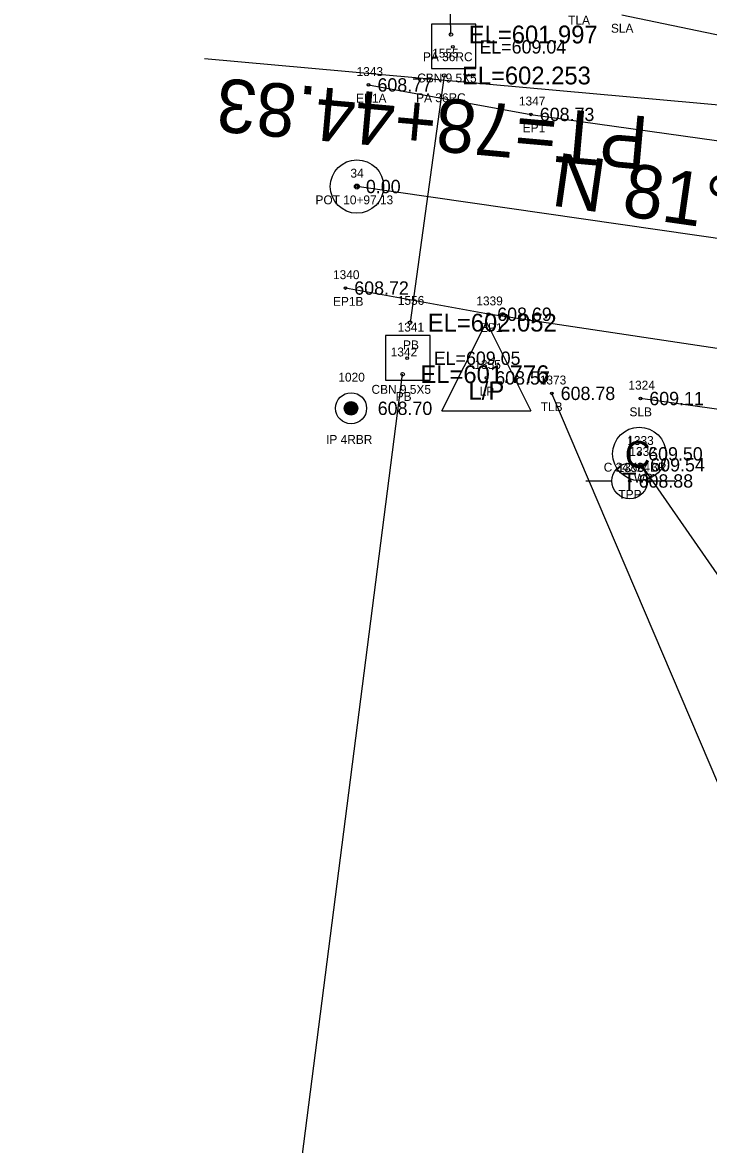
# Model space of a CAD drawing. Extents: x 1694813 to 1696862, y 1086485 to 1091027.
# Drawn here: x 1695695 to 1695772.2, y 1089855.4 to 1089981.5 of the extents above; entities that cross this region are included whole.
import ezdxf

# ---------------------------------------------------------------- set-up
doc = ezdxf.new("R2010")
doc.units = 0
for name, color, linetype in [('RD_EX_BldgApp', 7, 'Continuous'), ('RD_EX_BldgApp_txCode', 7, 'Continuous'), ('RD_EX_DR_Inlet', 7, 'Continuous'), ('RD_EX_DR_Inlet_txCode', 7, 'Continuous'), ('RD_EX_DR_Pipe', 7, 'Continuous'), ('RD_EX_DR_Pipe_txCode', 7, 'Continuous'), ('RD_EX_DV_Prop_txCode', 7, 'Continuous'), ('RD_EX_DV_PropPin', 7, 'Continuous'), ('RD_EX_Misc_txCode', 7, 'Continuous'), ('RD_EX_Road', 7, 'Continuous'), ('RD_EX_Road_txCode', 7, 'Continuous'), ('RD_EX_TX_BldgApp_ELEV', 7, 'Continuous'), ('RD_EX_TX_DR_Inlet_ELEV', 7, 'Continuous'), ('RD_EX_TX_DV_Prop_ELEV', 7, 'Continuous'), ('RD_EX_TX_Misc_ELEV', 7, 'Continuous'), ('RD_EX_TX_Road_ELEV', 7, 'Continuous'), ('RD_EX_TX_UT_ELEV', 7, 'Continuous'), ('RD_EX_TX_VEG_ELEV', 7, 'Continuous'), ('RD_EX_UT', 7, 'Continuous'), ('RD_EX_UT_txCode', 7, 'Continuous'), ('RD_EX_VEG', 7, 'Continuous'), ('RD_EX_VEG_txCode', 7, 'Continuous'), ('RD_HC_Cl', 7, 'Continuous'), ('RD_HC_Data', 7, 'Continuous'), ('RD_HC_Survey_ELEV', 7, 'Continuous'), ('RD_HC_txCode', 7, 'Continuous'), ('RD_SMD_Locator', 7, 'Continuous'), ('RD_TX_Pipe_ElevEX', 7, 'Continuous')]:
    doc.layers.add(name, color=color, linetype=linetype)

msp = doc.modelspace()

# ---------------------------------------------------------------- linework, layer by layer
at = {"layer": 'RD_EX_BldgApp'}
msp.add_line((1695785.88, 1089901.2), (1695764.63, 1089931.79), dxfattribs=at)
msp.add_circle((1695764.39, 1089933.02), 3, dxfattribs=at)
at = {"layer": 'RD_EX_DR_Inlet'}
for p, q in [((1695746, 1089976.32), (1695746, 1089981.32)), ((1695740.86, 1089941.32), (1695740.86, 1089946.32))]:
    msp.add_line(p, q, dxfattribs=at)
for points in [[(1695746, 1089976.32), (1695746, 1089981.32), (1695741, 1089981.32), (1695741, 1089976.32)], [(1695740.86, 1089941.32), (1695740.86, 1089946.32), (1695735.86, 1089946.32), (1695735.86, 1089941.32)]]:
    msp.add_lwpolyline(points, close=True, dxfattribs=at)
at = {"layer": 'RD_EX_DR_Pipe'}
for p, q in [((1695743.21, 1089980.16), (1695742.39, 1090020.71)), ((1695742.44, 1089975.55), (1695738.6, 1089947.77)), ((1695713.87, 1089755.91), (1695737.77, 1089941.97))]:
    msp.add_line(p, q, dxfattribs=at)
at = {"layer": 'RD_EX_DV_PropPin'}
for p, q in [((1695731.27, 1089937.84), (1695731.27, 1089938.44)), ((1695731.3, 1089937.77), (1695731.3, 1089938.51)), ((1695731.34, 1089937.71), (1695731.34, 1089938.57)), ((1695731.37, 1089937.66), (1695731.37, 1089938.61)), ((1695731.41, 1089937.62), (1695731.41, 1089938.65)), ((1695731.44, 1089937.59), (1695731.44, 1089938.69)), ((1695731.48, 1089937.56), (1695731.48, 1089938.72)), ((1695731.51, 1089937.53), (1695731.51, 1089938.75)), ((1695731.55, 1089937.5), (1695731.55, 1089938.77)), ((1695731.58, 1089937.48), (1695731.58, 1089938.79)), ((1695731.62, 1089937.46), (1695731.62, 1089938.81)), ((1695731.65, 1089937.45), (1695731.65, 1089938.83)), ((1695731.69, 1089937.43), (1695731.69, 1089938.85)), ((1695731.72, 1089937.42), (1695731.72, 1089938.86)), ((1695731.76, 1089937.41), (1695731.76, 1089938.87)), ((1695731.79, 1089937.4), (1695731.79, 1089938.88)), ((1695731.83, 1089937.39), (1695731.83, 1089938.89)), ((1695731.86, 1089937.38), (1695731.86, 1089938.89)), ((1695731.9, 1089937.38), (1695731.9, 1089938.9)), ((1695731.93, 1089937.38), (1695731.93, 1089938.9)), ((1695731.97, 1089937.38), (1695731.97, 1089938.9)), ((1695732, 1089937.38), (1695732, 1089938.9)), ((1695732.04, 1089937.38), (1695732.04, 1089938.9)), ((1695732.07, 1089937.38), (1695732.07, 1089938.89)), ((1695732.11, 1089937.39), (1695732.11, 1089938.89)), ((1695732.14, 1089937.4), (1695732.14, 1089938.88)), ((1695732.18, 1089937.41), (1695732.18, 1089938.87)), ((1695732.21, 1089937.42), (1695732.21, 1089938.86)), ((1695732.25, 1089937.43), (1695732.25, 1089938.85)), ((1695732.28, 1089937.45), (1695732.28, 1089938.83)), ((1695732.32, 1089937.46), (1695732.32, 1089938.81)), ((1695732.35, 1089937.48), (1695732.35, 1089938.79)), ((1695732.39, 1089937.5), (1695732.39, 1089938.77)), ((1695732.42, 1089937.53), (1695732.42, 1089938.75)), ((1695732.46, 1089937.56), (1695732.46, 1089938.72)), ((1695732.49, 1089937.59), (1695732.49, 1089938.69)), ((1695732.53, 1089937.62), (1695732.53, 1089938.65)), ((1695732.56, 1089937.66), (1695732.56, 1089938.61)), ((1695732.6, 1089937.71), (1695732.6, 1089938.57)), ((1695732.63, 1089937.77), (1695732.63, 1089938.51)), ((1695732.67, 1089937.84), (1695732.67, 1089938.44)), ((1695731.23, 1089937.94), (1695731.23, 1089938.33)), ((1695732.7, 1089937.94), (1695732.7, 1089938.33))]:
    msp.add_line(p, q, dxfattribs=at)
for radius in [1.75, 0.761]:
    msp.add_circle((1695731.97, 1089938.14), radius, dxfattribs=at)
at = {"layer": 'RD_EX_Road'}
for points in [[(1695733.94, 1089974.49), (1695752.2, 1089971.18), (1695799.58, 1089964.52), (1695808.15, 1089966.05), (1695812.58, 1089968.74), (1695812.72, 1089971.11), (1695815.83, 1089973.5), (1695820.51, 1089978.16)], [(1695814.71, 1089923.3), (1695809.51, 1089930.83), (1695802.46, 1089937.48), (1695803.12, 1089939.11), (1695792.87, 1089941.91), (1695747.41, 1089948.71), (1695731.33, 1089951.66)]]:
    msp.add_lwpolyline(points, dxfattribs=at)
at = {"layer": 'RD_EX_UT'}
for p, q in [((1695742.19, 1089937.84), (1695747.19, 1089947.84)), ((1695747.19, 1089947.84), (1695752.19, 1089937.84)), ((1695742.19, 1089937.84), (1695752.19, 1089937.84)), ((1695763.31, 1089935.04), (1695763.31, 1089931.97)), ((1695758.38, 1089929.98), (1695761.31, 1089929.98)), ((1695765.31, 1089929.98), (1695768.38, 1089929.98))]:
    msp.add_line(p, q, dxfattribs=at)
msp.add_circle((1695763.31, 1089929.97), 2, dxfattribs=at)
at = {"layer": 'RD_EX_VEG'}
for points in [[(1695762.44, 1089982.36), (1695791.84, 1089976.26), (1695804.67, 1089985.58), (1695805.61, 1090018.45), (1695818.68, 1090120.45), (1695830.78, 1090219.77), (1695838.1, 1090274.39)], [(1695703.52, 1089329.03), (1695695, 1089381.13), (1695696.39, 1089435.79), (1695702.88, 1089488.39), (1695714.38, 1089541.02), (1695736.44, 1089639.8), (1695727.2, 1089683.67), (1695743.97, 1089747.86), (1695756.74, 1089783.05), (1695766.78, 1089823.73), (1695779.53, 1089881.29), (1695754.55, 1089939.82)], [(1695775.83, 1089809.76), (1695787.59, 1089876.92), (1695797.35, 1089923.06), (1695786.71, 1089936.12), (1695764.52, 1089939.24)]]:
    msp.add_lwpolyline(points, dxfattribs=at)
at = {"layer": 'RD_HC_Cl'}
msp.add_line((1695828.78, 1089949.26), (1695732.63, 1089963.07), dxfattribs=at)
at = {"layer": 'RD_HC_Data'}
msp.add_line((1695830.5, 1089967.08), (1695715.49, 1089977.42), dxfattribs=at)
for radius in [3, 0.282]:
    msp.add_circle((1695732.63, 1089963.07), radius, dxfattribs=at)
at = {"layer": 'RD_SMD_Locator'}
for centre, radius in [((1695743.21, 1089980.16), 0.2), ((1695743.41, 1089978.77), 0.15), ((1695742.44, 1089975.55), 0.2), ((1695733.94, 1089974.49), 0.15), ((1695752.2, 1089971.18), 0.15), ((1695732.63, 1089963.07), 0.15), ((1695731.33, 1089951.66), 0.15), ((1695747.41, 1089948.71), 0.15), ((1695738.6, 1089947.77), 0.2), ((1695738.27, 1089943.77), 0.15), ((1695737.77, 1089941.97), 0.2), ((1695747.19, 1089941.56), 0.15), ((1695754.55, 1089939.82), 0.15), ((1695764.52, 1089939.24), 0.15), ((1695731.97, 1089938.14), 0.15), ((1695764.39, 1089933.02), 0.15), ((1695764.63, 1089931.79), 0.15), ((1695763.31, 1089929.97), 0.15)]:
    msp.add_circle(centre, radius, dxfattribs=at)

# ---------------------------------------------------------------- texts
at = {"layer": 'RD_EX_BldgApp'}
msp.add_text('C', height=3, dxfattribs=at).set_placement((1695762.76, 1089931.46))
at = {"layer": 'RD_EX_BldgApp_txCode'}
for s, p in [('1333', (1695763.04, 1089934.02)), ('C 24X24BR', (1695760.39, 1089931.02))]:
    msp.add_text(s, height=1, dxfattribs=at).set_placement(p)
at = {"layer": 'RD_EX_DR_Inlet_txCode'}
for s, p in [('CBN 9 5X5', (1695739.41, 1089974.77)), ('1341', (1695737.21, 1089946.77)), ('CBN 9 5X5', (1695734.27, 1089939.77))]:
    msp.add_text(s, height=1, dxfattribs=at).set_placement(p)
at = {"layer": 'RD_EX_DR_Pipe_txCode'}
for s, p in [('PA 36RC', (1695740.06, 1089977.16)), ('1555', (1695741.09, 1089977.55)), ('PA 36RC', (1695739.29, 1089972.55)), ('1556', (1695737.23, 1089949.77)), ('1342', (1695736.43, 1089943.97)), ('PB', (1695737.82, 1089944.77)), ('PB', (1695736.99, 1089938.97))]:
    msp.add_text(s, height=1, dxfattribs=at).set_placement(p)
at = {"layer": 'RD_EX_DV_Prop_txCode'}
for s, p in [('1020', (1695730.54, 1089941.14)), ('IP 4RBR', (1695729.16, 1089934.14))]:
    msp.add_text(s, height=1, dxfattribs=at).set_placement(p)
at = {"layer": 'RD_EX_Misc_txCode'}
for s, p in [('1332', (1695763.28, 1089932.79)), ('WB', (1695763.79, 1089929.79))]:
    msp.add_text(s, height=1, dxfattribs=at).set_placement(p)
at = {"layer": 'RD_EX_Road_txCode'}
for s, p in [('1343', (1695732.59, 1089975.49)), ('EP1A', (1695732.53, 1089972.49)), ('1347', (1695750.85, 1089972.18)), ('EP1', (1695751.28, 1089969.18)), ('1340', (1695729.94, 1089952.66)), ('EP1B', (1695729.94, 1089949.66)), ('1339', (1695746.06, 1089949.71)), ('EP1', (1695746.48, 1089946.71))]:
    msp.add_text(s, height=1, dxfattribs=at).set_placement(p)
at = {"layer": 'RD_EX_TX_BldgApp_ELEV'}
msp.add_text('609.50', height=1.5, dxfattribs=at).set_placement((1695765.39, 1089932.27))
at = {"layer": 'RD_EX_TX_DR_Inlet_ELEV'}
for s, p in [('EL=609.04', (1695746.41, 1089978.02)), ('EL=609.05', (1695741.27, 1089943.02))]:
    msp.add_text(s, height=1.5, dxfattribs=at).set_placement(p)
at = {"layer": 'RD_EX_TX_DV_Prop_ELEV'}
msp.add_text('608.70', height=1.5, dxfattribs=at).set_placement((1695734.97, 1089937.39))
at = {"layer": 'RD_EX_TX_Misc_ELEV'}
msp.add_text('609.54', height=1.5, dxfattribs=at).set_placement((1695765.63, 1089931.04))
at = {"layer": 'RD_EX_TX_Road_ELEV'}
for s, p in [('608.77', (1695734.94, 1089973.74)), ('608.73', (1695753.2, 1089970.43)), ('608.72', (1695732.33, 1089950.91)), ('608.69', (1695748.41, 1089947.96))]:
    msp.add_text(s, height=1.5, dxfattribs=at).set_placement(p)
at = {"layer": 'RD_EX_TX_UT_ELEV'}
for s, p in [('608.57', (1695748.19, 1089940.81)), ('608.88', (1695764.31, 1089929.22))]:
    msp.add_text(s, height=1.5, dxfattribs=at).set_placement(p)
at = {"layer": 'RD_EX_TX_VEG_ELEV'}
for s, p in [('608.78', (1695755.55, 1089939.07)), ('609.11', (1695765.52, 1089938.49))]:
    msp.add_text(s, height=1.5, dxfattribs=at).set_placement(p)
at = {"layer": 'RD_EX_UT'}
for s, p in [('L/P', (1695745.18, 1089939.12)), ('T', (1695762.46, 1089928.92))]:
    msp.add_text(s, height=2, dxfattribs=at).set_placement(p)
at = {"layer": 'RD_EX_UT_txCode'}
for s, p in [('1355', (1695745.84, 1089942.56)), ('LP', (1695746.43, 1089939.56)), ('1356', (1695761.94, 1089930.97)), ('TPP', (1695762.04, 1089927.97))]:
    msp.add_text(s, height=1, dxfattribs=at).set_placement(p)
at = {"layer": 'RD_EX_VEG_txCode'}
for s, p in [('TLA', (1695756.39, 1089981.28)), ('SLA', (1695761.2, 1089980.36)), ('1373', (1695753.2, 1089940.82)), ('1324', (1695763.17, 1089940.24)), ('TLB', (1695753.31, 1089937.82)), ('SLB', (1695763.29, 1089937.24))]:
    msp.add_text(s, height=1, dxfattribs=at).set_placement(p)
at = {"layer": 'RD_HC_Data'}
for s, rotation, p in [('PT=78+44.83', 174.8618, (1695765.58, 1089970.91)), ('N 81%%d 49\' 21" W', 351.8225, (1695754.36, 1089960.96))]:
    msp.add_text(s, height=6, rotation=rotation, dxfattribs=at).set_placement(p)
at = {"layer": 'RD_HC_Survey_ELEV'}
msp.add_text('0.00', height=1.5, dxfattribs=at).set_placement((1695733.64, 1089962.32))
at = {"layer": 'RD_HC_txCode'}
for s, p in [('34', (1695731.9, 1089964.07)), ('POT 10+97.13', (1695727.97, 1089961.07))]:
    msp.add_text(s, height=1, dxfattribs=at).set_placement(p)
at = {"layer": 'RD_TX_Pipe_ElevEX'}
for s, p in [('EL=601.997', (1695745.21, 1089979.16)), ('EL=602.253', (1695744.44, 1089974.55)), ('EL=602.052', (1695740.6, 1089946.77)), ('EL=601.776', (1695739.77, 1089940.97))]:
    msp.add_text(s, height=2, dxfattribs=at).set_placement(p)

doc.saveas('drawing.dxf')
